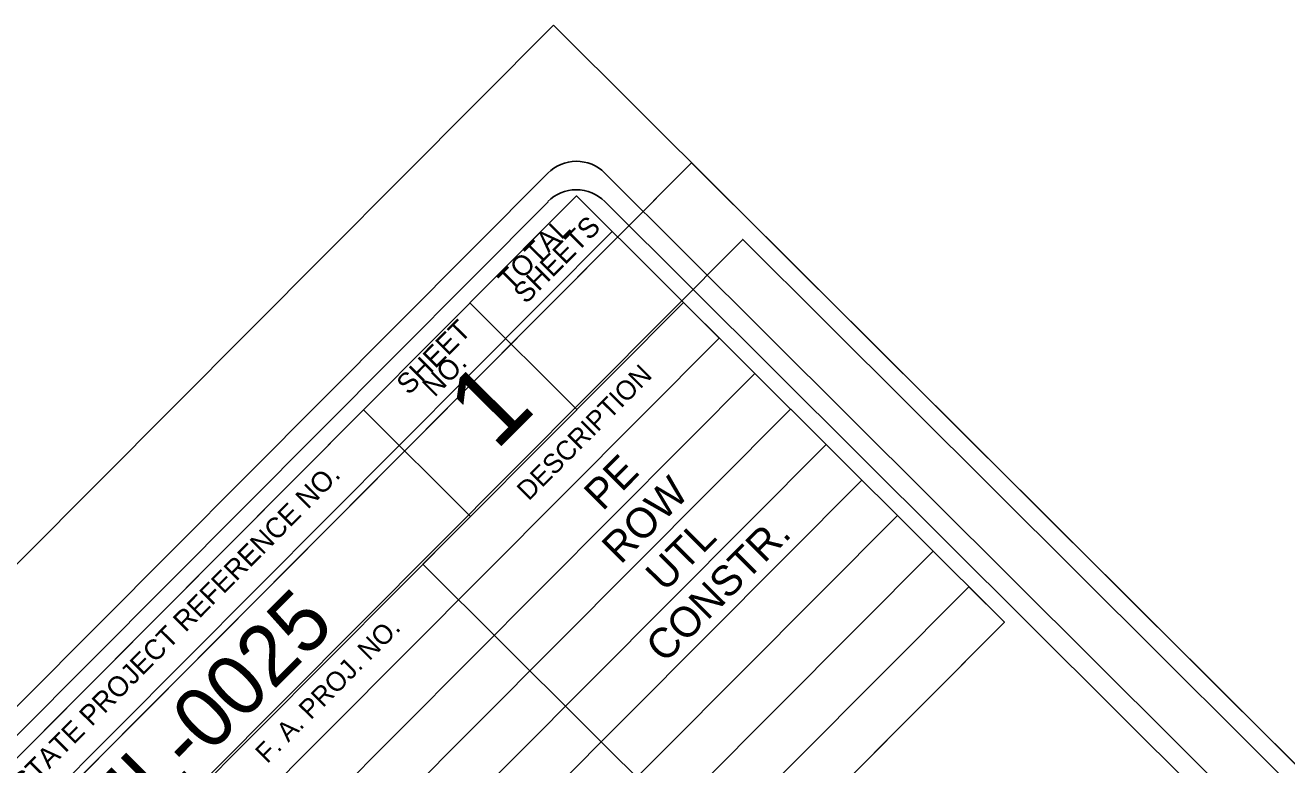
# Model space of a CAD drawing. Extents: x 1481763 to 1495577, y 493394 to 506245.
# Drawn here: x 1488088 to 1489028, y 500935 to 501486 of the extents above; entities that cross this region are included whole.
import ezdxf

# ---------------------------------------------------------------- set-up
doc = ezdxf.new("R2010")
doc.units = 0
for name, color, linetype in [('Sheet Cutting Line CELL', 7, 'Continuous'), ('Sheet Data Field CELL', 7, 'Continuous'), ('Sheet Plot Border Inside CELL', 7, 'Continuous'), ('Sheet Plot Border Outside CELL', 7, 'Continuous'), ('Sheet Title CELL', 7, 'Continuous')]:
    doc.layers.add(name, color=color, linetype=linetype)

msp = doc.modelspace()

# ---------------------------------------------------------------- linework, layer by layer
at = {"layer": 'Sheet Cutting Line CELL'}
msp.add_line((1485019.38, 497803.89), (1488584.25, 501383.61), dxfattribs=at)
msp.add_lwpolyline([(1485019.38, 497803.89), (1488584.25, 501383.61), (1490922.52, 499055.04), (1487357.65, 495475.32)], close=True, dxfattribs=at)
at = {"layer": 'Sheet Plot Border Inside CELL'}
msp.add_lwpolyline([(1487337.48, 495550.45), (1490865.3, 499092.97), (1488622.45, 501326.52), (1485094.62, 497784)], close=True, dxfattribs=at)
at = {"layer": 'Sheet Plot Border Outside CELL'}
msp.add_lwpolyline([(1488481.29, 501486.15), (1484916.42, 497906.42), (1487254.69, 495577.85), (1490819.56, 499157.58)], close=True, dxfattribs=at)
at = {"layer": 'Sheet Title CELL'}
for points in [[(1488477.3, 501375.85), (1485344.2, 498229.75)], [(1490709.17, 499195.53), (1488519.7, 501375.92)], [(1487942.92, 500747.89), (1488525.07, 501332.47), (1488498.5, 501358.93), (1487916.37, 500774.33), (1488235.21, 500456.82), (1488429.25, 500651.61), (1488190.1, 500889.77), (1488075.47, 500774.66)], [(1487995.73, 500854.07), (1488339.78, 501199.5), (1488419.44, 501120.11), (1488384.09, 501084.62), (1488623.24, 500846.46), (1488817.36, 501041.39), (1488498.5, 501358.93), (1488419.11, 501279.21), (1488498.85, 501199.86)], [(1488477.32, 501354.61), (1485471.34, 498336.11)], [(1490294.73, 499587.09), (1488519.72, 501354.73)], [(1488022.66, 500668.48), (1488604.81, 501253.06), (1488578.21, 501279.54), (1487996.06, 500694.97)], [(1488235.21, 500456.82), (1488817.36, 501041.39), (1488790.81, 501067.83), (1488208.64, 500483.28), (1488182.09, 500509.71), (1488764.24, 501094.29), (1488737.67, 501120.75), (1488155.55, 500536.2), (1488128.92, 500562.66), (1488711.07, 501147.24), (1488684.5, 501173.7), (1488102.35, 500589.12), (1488075.8, 500615.56), (1488657.93, 501200.16), (1488631.38, 501226.6), (1488049.23, 500642.02)]]:
    msp.add_lwpolyline(points, dxfattribs=at)
for centre in [(1488498.42, 501354.79), (1488498.46, 501333.58)]:
    msp.add_arc(centre, 30, 45.11911, 135.11911, dxfattribs=at)

# ---------------------------------------------------------------- texts
at = {"layer": 'Sheet Data Field CELL'}
for s, height, p in [('PE', 22.5, (1488518.04, 501123.62)), ('ROW', 22.5, (1488531.43, 501083.93)), ('UTL', 22.5, (1488564.12, 501063.23)), ('CONSTR.', 22.5, (1488564.15, 501010.13)), ('HL-0025', 45, (1488156.75, 500874.13))]:
    msp.add_text(s, height=height, rotation=45.11911, dxfattribs=at).set_placement(p)
at = {"layer": 'Sheet Title CELL'}
for s, height, p in [('SHEETS', 14.999, (1488460.77, 501277.89)), ('TOTAL', 14.999, (1488449.43, 501287.76)), ('SHEET', 14.999, (1488373.57, 501210.04)), ('NO.', 14.999, (1488392.85, 501208.41)), ('1', 58.05, (1488438.44, 501168.31)), ('DESCRIPTION', 14.4, (1488462.93, 501131.21)), ('STATE PROJECT REFERENCE NO.', 14.9994, (1488087.6, 500913.31)), ('F. A. PROJ. NO.', 14.4, (1488267.94, 500935.46))]:
    msp.add_text(s, height=height, rotation=45.11911, dxfattribs=at).set_placement(p)

doc.saveas('drawing.dxf')
